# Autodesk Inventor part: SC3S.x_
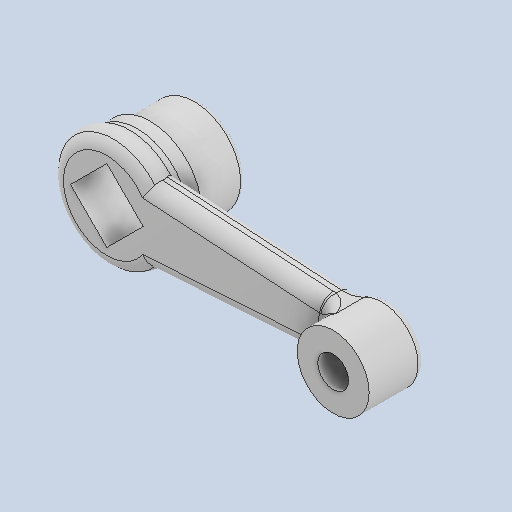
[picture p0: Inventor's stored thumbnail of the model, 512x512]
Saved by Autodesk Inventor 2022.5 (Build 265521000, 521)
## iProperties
Created: 2024-02
Part Number: SC3S.x_
Material: 一般
Document SubType Name: Modeling
Designer: ImaoCorp
Density: 1 g/cm^3
Appearance: 既定
Author: ImaoCorp
Sending System: SOLIDWORKS 2022-2022290
MC: AMD64
MC_MODEL: Intel64 Family 6 Model 60 Stepping 3, GenuineIntel
OS: Windows_NT
FRU: Parasolid Version 33.1, build 260,  4-25-2022
FORMAT: text
GUISE: transmit
KEY: FILESC3S.x_t
DATE: Tue Feb 27 12:01:34 2024
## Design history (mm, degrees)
feature "Base1"
node "ソリッド1"
